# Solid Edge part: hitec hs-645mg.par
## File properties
Author: nakano
Template: iso metric part.par
Last saved by: nakano
Revision: 4
Application: Solid Edge
Density: 1663.77712904019 kg/m^3
Accuracy: 0.990
Username: nakano
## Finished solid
Body 1: solid body, 276 faces, 760 edges, 494 vertices.
  Faces by surface: plane 198, cylinder 72, torus 4, cone 2
  Edges by curve: line 472, circle 156, spline 60, intersection 48, ellipse 24
Bounding box of the edges (mm; curved faces can reach further): 19.800 x 60.800 x 41.860, from (-9.9, -34.15, 0) to (9.9, 26.65, 41.86).
Cylindrical faces by radius (mm): R0.5 x20, R0.8 x4, R0.95 x1, R1.2815 x4, R1.8 x5, R2 x4, R2.6 x30, R5.1249 x1, R5.6 x1, R6.5 x1, R9.9 x1
Conical faces (half-angle, radius in mm at the cone's reference point): 45 deg R1.1 x1, 60.664 deg R2.8657 x1
Toroidal faces (ring radius, tube radius in mm): R0.7815 r0.5 x4
Planar faces by outward normal: +x 21, +y 20, +z 15, -x 21, -y 24, -z 27, oblique 70
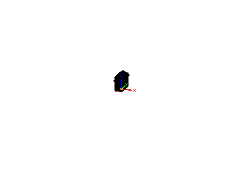
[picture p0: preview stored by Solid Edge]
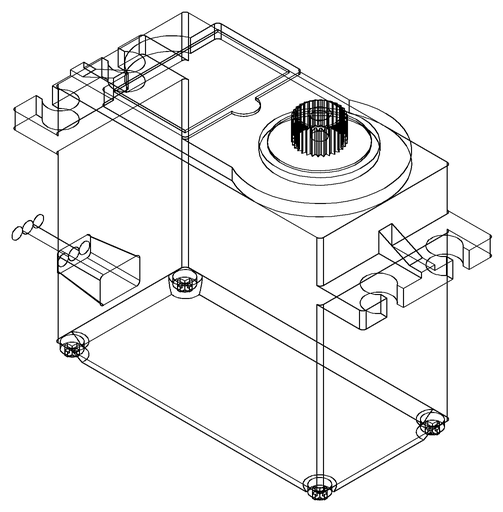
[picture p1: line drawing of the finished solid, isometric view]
